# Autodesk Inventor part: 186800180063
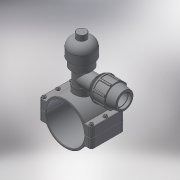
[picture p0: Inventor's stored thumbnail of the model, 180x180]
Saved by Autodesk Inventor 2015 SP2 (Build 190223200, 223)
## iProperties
Created: 2017-05
Part Number: 186800180063
Material: Generic
Description: PLASSON MECHANICAL TAPPING VALVE 180-63
Document SubType Name: Modeling
Designer: KIM
Density: 1 g/cm^3
Appearance: Default
Author: KIM
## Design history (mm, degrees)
derived "18680.ipt"
feature "Solid1::18680.ipt"
feature "Solid2::18680.ipt"
tag "TaggingFeature1"
body "Solid1"
other parameters: "d0" = 198, "d1" = 245, "d4" = 154, "d5" = 0, "d6" = 12.25, "d7" = 245, "d8" = 0.1, "d10" = 0, "d11" = 1.8, "d14" = 73.6528, "d20" = 1.8, "d23" = 1.8, "d36" = 15, "d37" = 12, "d38" = 98, "d39" = 0, "d40" = 3, "d41" = 5, "d42" = 0, "d44" = 3, "d45" = 0, "d46" = 1.8, "d51" = 122, "d52" = 56.656, "d53" = 21, "d54" = 0, "d57" = 0, "d58" = 194.4, "d60" = 0, "d62" = 15, "d63" = 12, "d67" = 63, "d68" = 16.66667, "d70" = 113, "d71" = 84.75, "d72" = 2.85714, "d73" = 90.4, "d74" = 120 deg, "d75" = 81.9, "d76" = 10 deg, "d77" = 101.7, "d80" = 50.4, "d82" = 11, "d87" = 28.57143, "d90" = 105.09, "d91" = 35 deg, "d92" = 17.5 deg, "d94" = 0, "d96" = 360 deg, "d98" = 1.26, "d99" = 121, "d100" = 67.8, "d101" = 135 deg, "d102" = 2.26, "d105" = 5.65, "d106" = 0, "d107" = 0.1, "d109" = 73.6528, "d112" = 34.85714, "d113" = 6.66667, "d116" = 0, "d121" = 67.9872, "d122" = 113.312, "d123" = 96.3152, "d124" = 45 deg, "d125" = 219.6, "d126" = 244, "d127" = 146.4, "d128" = 1, "d129" = 65, "G_" = 56.656, "A_" = 122, "L_" = 245, "L_1" = 154, "l_2" = 21, "d_1" = 63, "E_" = 113, "H_1" = 65, "H_2" = 244
